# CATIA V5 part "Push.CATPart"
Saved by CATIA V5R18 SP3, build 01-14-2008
Part number: Table Center Axis02
Bounding box of the stored display mesh (mm): x -32.499 to 32.499, y -12 to 86, z -32.499 to 32.499
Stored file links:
  E:\#00 CATIA V5 Movie\#03 CATIA V5 Data\#07 KIN\Balance Unit (1)\Push.CATPart
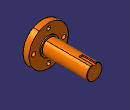
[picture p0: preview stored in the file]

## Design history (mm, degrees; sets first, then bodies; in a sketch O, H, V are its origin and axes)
Body1 (main body)
  Sketch1 on yz-plane, origin (0, 0, 0), H (0, 1, 0), V (0, 0, 1)
    point P1 (-12, 0)
    line L1 (-12, 0) -> (-12, 12.5)
    line L2 (-12, 12.5) -> (0, 12.5)
    line L3 (0, 12.5) -> (0, 32.5)
    line L4 (0, 32.5) -> (10, 32.5)
    line L5 (10, 32.5) -> (10, 15)
    line L6 (10, 15) -> (12, 15)
    point P7 (12, 15)
    line L7 (12, 15) -> (12, 12.5)
    point P8 (12, 12.5)
    line L8 (12, 12.5) -> (86, 12.5)
    line L9 (86, 12.5) -> (86, 0)
    point P10 (86, 0)
    distance L3 L9 = 86
    distance L1 L3 = 12
    length L4 = 10
    distance L7 L3 = 12
    distance P7 H = 15
    distance L8 H = 12.5
    distance L3 V = 0
    distance L4 H = 32.5
    coincidence: P1 H, P8 L2, P10 H
    vertical: L1 V, L3 V, L5 V, L7 V, L9 V
    horizontal: L2 H, L4 H, L6 H, L8 H
  Shaft1: profile Sketch1, axis Sketch1.H, angle 360
  Chamfer1: length 0.5, second length 0.5, on face of Shaft1 from Sketch1.L9; edge [face of Shaft1 from Sketch1.L1 | face of Shaft1 from Sketch1.L2]
  Sketch2 on face of Shaft1 from Sketch1.L9, origin (0, 86, 0), H (-1, 0, 0), V (0, 0, 1)
    line L1 (-3, 10) -> (3, 10)
    line L2 (3, 10) -> (3, 17)
    line L3 (3, 17) -> (-3, 17)
    line L4 (-3, 17) -> (-3, 10)
    reference projected circle E1 centre (0, 0) radius 12.5 from edge [face of Shaft1 from Sketch1.L8 | face of Chamfer1]
    length L1 = 6
    distance L1 E1 = 22.5
    distance L3 L1 = 7
    horizontal: L1 H, L3 H
    vertical: L2 V, L4 V
    symmetry: L2 L4 V
  Pocket1: profile Sketch2, direction (0, -1, 0), length 23
  Sketch3 on face of Shaft1 from Sketch1.L5, origin (0, 10, 25), H (1, 0, 0), V (0, 0, -1)
    point P1 (0, 0)
    reference projected point E1 (0, 0) from Sketch4.P1
    coincidence: E1 P1
  Hole1: placed by Sketch3, at (0, 10, 25) direction (0, -1, 0), diameter 6.917, depth 10, threaded "M8", thread diameter 8, thread depth 10, pitch 1
  CircPattern1: of Hole1, instances 4, angular step 90, axis from zx-plane
  Sketch4 on face of Shaft1 from Sketch1.L5, origin (0, 10, 0), H (-1, 0, 0), V (0, 0, 1)
    point P1 (0, 25)
    distance P1 H = 25
    coincidence: P1 V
